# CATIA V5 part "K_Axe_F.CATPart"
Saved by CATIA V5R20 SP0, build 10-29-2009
Part number: Axe_F
Bounding box of the stored display mesh (mm): x -7.5 to 7.5, y -7.49 to 7.49, z 0 to 65.338
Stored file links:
  G:\Khaled_CFAO_2011\ST2M\ST2M_GR2\echouteau\Khaled\CAD_ThinkMotion\K_Axe_F.CATPart
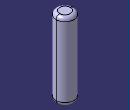
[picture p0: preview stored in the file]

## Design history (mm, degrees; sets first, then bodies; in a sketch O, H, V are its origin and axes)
AxisSystem1: origin (0, 0, 0), X (1, 0, 0), Y (0, 1, 0), Z (0, 0, 1)
Body1 (main body)
  Sketch1 on XY plane of AxisSystem1, origin (0, 0, 0), H (1, 0, 0), V (0, 1, 0)
    circle A1 centre (0, 0) radius 7.5
    radius A1 = 7.5
  Pad1: profile Sketch1, direction (0, 0, 1), length 65.338
  Fillet1: radius 3, on end face of Pad1
  Fillet2: radius 3, on edge [start face of Pad1 | face of Pad1 from Sketch1.A1]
